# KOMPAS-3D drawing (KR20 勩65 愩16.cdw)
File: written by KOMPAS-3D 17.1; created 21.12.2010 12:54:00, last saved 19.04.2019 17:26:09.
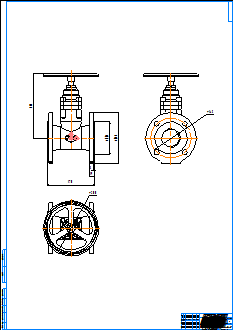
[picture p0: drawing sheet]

Title block, sheet 1: name: KR20 Ду65 Ру16; material: Внимание! Данный продукт является объектом авторского права ООО «Торговый Дом АДЛ». / Запрещается изменение, копирование, распространение / (в том числе путем копирования на другие сайты и ресурсы в Интернете) / или любое иное использование информации и объектов без предварительного / согласия правообладателя (ООО «Торговый Дом АДЛ»).; scale: 1:1; sheets: 1; organisation: ООО "Торговый дом АДЛ"; sheet format: A0; stored path: \\adlc.lan\data\АДЛ_ПКД\3D-модели\ADL production\Клиновые задвижки серии KR ГРАНАР\Клиновые задвижки KR20\KOMPAS 2D\KR20 Ду65 Ру16.cdw

Views: Спереди 1, Проекционный вид 2, Проекционный вид 3
Dimensions and other numbers on the sheet: 118; 185; 3; 19; 170; 232; 145; 200; 1:1; 1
